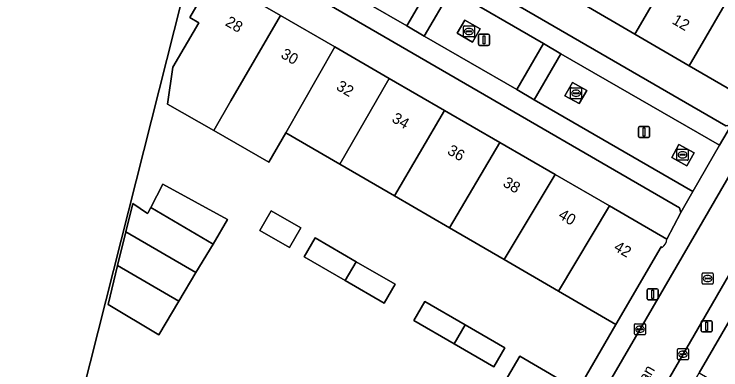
# Model space of a CAD drawing. Extents: x 160023 to 161302, y 384750 to 385707.
# Drawn here: x 160259.3 to 160323.3, y 385038.4 to 385070.6 of the extents above; entities that cross this region are included whole.
import ezdxf

# ---------------------------------------------------------------- set-up
doc = ezdxf.new("R2010")
doc.units = 0
for name, color, linetype in [('IMGEO_Erf', 7, 'Continuous'), ('IMGEO_Grasland_overig', 7, 'Continuous'), ('IMGEO_Groenvoorziening', 7, 'Continuous'), ('IMGEO_Hek', 7, 'Continuous'), ('IMGEO_Kolk', 7, 'Continuous'), ('IMGEO_Lichtmast', 7, 'Continuous'), ('IMGEO_Muur', 7, 'Continuous'), ('IMGEO_Openbare_ruimte_label', 7, 'Continuous'), ('IMGEO_Pand', 7, 'Continuous'), ('IMGEO_Pand_nummerreeks', 7, 'Continuous'), ('IMGEO_Rijbaan_lokaal_open', 7, 'Continuous'), ('IMGEO_Rioolput', 7, 'Continuous'), ('IMGEO_Voetpad_open', 7, 'Continuous')]:
    doc.layers.add(name, color=color, linetype=linetype)

msp = doc.modelspace()

# ---------------------------------------------------------------- linework, layer by layer
at = {"layer": 'IMGEO_Erf'}
for points in [[(160293.095, 385145.525), (160266.916, 385041.926), (160261.202, 385019.264)], [(160278.83, 385086.496), (160323.699, 385060.519), (160324.22, 385060.605), (160325.557, 385062.957), (160320.404, 385065.947), (160315.483, 385068.802), (160310.552, 385071.662)], [(160278.193, 385073.523), (160283.41, 385070.503), (160288.342, 385067.649), (160293.266, 385064.799), (160298.25, 385061.914), (160303.277, 385059.004), (160308.254, 385056.123), (160313.176, 385053.274), (160318.364, 385050.271), (160319.638, 385052.685), (160319.512, 385053.082), (160276.629, 385077.974)], [(160309.764, 385035.682), (160313.763, 385042.544), (160308.557, 385045.567), (160303.656, 385048.412), (160298.712, 385051.282), (160293.738, 385054.17), (160288.784, 385057.046), (160283.9, 385059.882), (160282.379, 385057.222), (160277.378, 385060.082), (160273.2, 385062.472), (160273.687, 385065.811), (160276.023, 385069.833), (160275.211, 385070.305), (160277.161, 385073.661)], [(160303.969, 385037.777), (160305.078, 385039.676), (160308.618, 385037.609)]]:
    msp.add_lwpolyline(points, dxfattribs=at)
for points in [[(160277.317, 385049.825), (160275.767, 385047.232), (160274.218, 385044.64), (160272.405, 385041.605), (160267.824, 385044.342), (160268.686, 385047.875), (160269.434, 385050.937), (160270.054, 385053.478), (160271.401, 385052.58), (160271.415, 385052.602), (160271.684, 385053.12), (160272.786, 385055.244), (160278.636, 385052.033)], [(160281.548, 385051.053), (160282.565, 385052.826), (160285.266, 385051.276), (160284.249, 385049.503)], [(160285.558, 385048.661), (160286.549, 385050.376), (160290.273, 385048.224), (160293.793, 385046.189), (160292.802, 385044.474), (160289.276, 385046.512)], [(160296.467, 385044.618), (160300.131, 385042.501), (160303.711, 385040.431), (160302.72, 385038.716), (160299.116, 385040.799), (160295.476, 385042.903)]]:
    msp.add_lwpolyline(points, close=True, dxfattribs=at)
at = {"layer": 'IMGEO_Grasland_overig'}
msp.add_lwpolyline([(160263.258, 385128.704), (160254.185, 385092.511), (160247.686, 385066.356), (160240.011, 385035.841), (160232.89, 385007.459), (160237.23, 385006.236), (160253.525, 385012.336), (160257.45, 385014.824), (160260.583, 385016.811), (160261.202, 385019.264), (160266.916, 385041.926), (160293.095, 385145.525)], dxfattribs=at)
at = {"layer": 'IMGEO_Groenvoorziening'}
for points in [[(160283.409, 385081.75), (160280.973, 385077.566), (160294.841, 385069.555), (160297.275, 385073.716)], [(160298.861, 385072.807), (160296.418, 385068.634), (160304.793, 385063.794), (160307.217, 385067.951)], [(160299.392, 385068.892), (160300.083, 385070.085), (160301.474, 385069.29), (160300.786, 385068.091)], [(160308.793, 385067.033), (160306.362, 385062.878), (160320.723, 385054.571), (160323.131, 385058.752)], [(160309.152, 385063.222), (160309.83, 385064.427), (160311.131, 385063.723), (160310.452, 385062.522)], [(160318.809, 385057.635), (160319.458, 385058.836), (160320.847, 385058.076), (160320.177, 385056.886)]]:
    msp.add_lwpolyline(points, close=True, dxfattribs=at)
at = {"layer": 'IMGEO_Hek'}
for points in [[(160293.095, 385145.525), (160266.916, 385041.926)], [(160261.202, 385019.264), (160266.916, 385041.926)]]:
    msp.add_lwpolyline(points, dxfattribs=at)
at = {"layer": 'IMGEO_Kolk'}
for p, q in [((160299.964, 385068.628), (160299.964, 385069.48)), ((160300.039, 385069.554), (160300.891, 385069.554)), ((160300.965, 385069.48), (160300.965, 385068.628)), ((160300.223, 385069.048), (160300.223, 385069.06)), ((160300.661, 385069.011), (160300.263, 385069.011)), ((160300.266, 385069.097), (160300.664, 385069.097)), ((160300.475, 385068.774), (160300.45, 385068.774)), ((160300.452, 385069.334), (160300.477, 385069.334)), ((160300.707, 385069.06), (160300.707, 385069.048)), ((160300.891, 385068.554), (160300.039, 385068.554)), ((160309.66, 385063.034), (160309.66, 385063.886)), ((160309.735, 385063.96), (160310.587, 385063.96)), ((160310.148, 385063.74), (160310.173, 385063.74)), ((160310.661, 385063.886), (160310.661, 385063.034)), ((160309.919, 385063.454), (160309.919, 385063.466)), ((160310.357, 385063.417), (160309.959, 385063.417)), ((160309.962, 385063.503), (160310.36, 385063.503)), ((160310.171, 385063.18), (160310.146, 385063.18)), ((160310.403, 385063.466), (160310.403, 385063.454)), ((160310.587, 385062.96), (160309.735, 385062.96)), ((160319.288, 385057.471), (160319.288, 385058.323)), ((160319.363, 385058.397), (160320.215, 385058.397)), ((160319.547, 385057.891), (160319.547, 385057.903)), ((160319.59, 385057.94), (160319.988, 385057.94)), ((160319.776, 385058.177), (160319.801, 385058.177)), ((160320.031, 385057.903), (160320.031, 385057.891)), ((160320.289, 385058.323), (160320.289, 385057.471)), ((160320.215, 385057.397), (160319.363, 385057.397)), ((160319.985, 385057.854), (160319.587, 385057.854)), ((160319.799, 385057.617), (160319.774, 385057.617)), ((160315.44, 385041.684), (160315.44, 385042.536)), ((160315.515, 385042.61), (160316.367, 385042.61)), ((160316.441, 385042.536), (160316.441, 385041.684)), ((160315.699, 385042.104), (160315.699, 385042.116)), ((160316.137, 385042.067), (160315.739, 385042.067)), ((160315.742, 385042.153), (160316.14, 385042.153)), ((160315.928, 385042.39), (160315.953, 385042.39)), ((160316.183, 385042.116), (160316.183, 385042.104)), ((160316.367, 385041.61), (160315.515, 385041.61)), ((160315.951, 385041.83), (160315.926, 385041.83)), ((160319.333, 385039.435), (160319.333, 385040.287)), ((160319.408, 385040.361), (160320.26, 385040.361)), ((160319.821, 385040.141), (160319.846, 385040.141)), ((160320.334, 385040.287), (160320.334, 385039.435)), ((160320.26, 385039.361), (160319.408, 385039.361)), ((160319.592, 385039.855), (160319.592, 385039.867)), ((160320.03, 385039.818), (160319.632, 385039.818)), ((160319.635, 385039.904), (160320.033, 385039.904)), ((160319.844, 385039.581), (160319.819, 385039.581)), ((160320.076, 385039.867), (160320.076, 385039.855))]:
    msp.add_line(p, q, dxfattribs=at)
for points in [[(160299.964, 385068.628), (160299.964, 385069.48)], [(160300.039, 385069.554), (160300.891, 385069.554)], [(160300.965, 385069.48), (160300.965, 385068.628)], [(160300.891, 385068.554), (160300.039, 385068.554)], [(160309.66, 385063.034), (160309.66, 385063.886)], [(160309.735, 385063.96), (160310.587, 385063.96)], [(160310.661, 385063.886), (160310.661, 385063.034)], [(160310.587, 385062.96), (160309.735, 385062.96)], [(160319.288, 385057.471), (160319.288, 385058.323)], [(160319.363, 385058.397), (160320.215, 385058.397)], [(160320.289, 385058.323), (160320.289, 385057.471)], [(160320.215, 385057.397), (160319.363, 385057.397)], [(160315.44, 385041.684), (160315.44, 385042.536)], [(160315.515, 385042.61), (160316.367, 385042.61)], [(160316.441, 385042.536), (160316.441, 385041.684)], [(160316.367, 385041.61), (160315.515, 385041.61)], [(160319.333, 385039.435), (160319.333, 385040.287)], [(160319.408, 385040.361), (160320.26, 385040.361)], [(160320.334, 385040.287), (160320.334, 385039.435)], [(160320.26, 385039.361), (160319.408, 385039.361)]]:
    msp.add_lwpolyline(points, dxfattribs=at)
for centre, radius, start, end in [((160300.041, 385069.478), 0.0765, 91.55205, 178.44795), ((160300.041, 385069.478), 0.0765, 91.55205, 178.44795), ((160300.889, 385069.478), 0.0765, 1.55205, 88.44795), ((160300.889, 385069.478), 0.0765, 1.55205, 88.44795), ((160300.263, 385069.057), 0.0403, 85.87752, 175.75265), ((160300.26, 385069.047), 0.0366, 178.93798, 274.71019), ((160300.664, 385069.054), 0.043, 264.86636, 352.45326), ((160300.668, 385069.059), 0.0386, 1.73085, 96.63898), ((160300.041, 385068.63), 0.0765, 181.55205, 268.44795), ((160300.041, 385068.63), 0.0765, 181.55205, 268.44795), ((160300.889, 385068.63), 0.0765, 271.55205, 358.44795), ((160300.889, 385068.63), 0.0765, 271.55205, 358.44795), ((160309.737, 385063.884), 0.0765, 91.55205, 178.44795), ((160309.737, 385063.884), 0.0765, 91.55205, 178.44795), ((160310.585, 385063.884), 0.0765, 1.55205, 88.44795), ((160310.585, 385063.884), 0.0765, 1.55205, 88.44795), ((160309.737, 385063.036), 0.0765, 181.55205, 268.44795), ((160309.737, 385063.036), 0.0765, 181.55205, 268.44795), ((160309.959, 385063.463), 0.0403, 85.87752, 175.75265), ((160309.956, 385063.453), 0.0366, 178.93798, 274.71019), ((160310.36, 385063.46), 0.043, 264.86636, 352.45326), ((160310.364, 385063.465), 0.0386, 1.73085, 96.63898), ((160310.585, 385063.036), 0.0765, 271.55205, 358.44795), ((160310.585, 385063.036), 0.0765, 271.55205, 358.44795), ((160319.365, 385058.321), 0.0765, 91.55205, 178.44795), ((160319.365, 385058.321), 0.0765, 91.55205, 178.44795), ((160319.587, 385057.9), 0.0403, 85.87752, 175.75265), ((160319.584, 385057.89), 0.0366, 178.93798, 274.71019), ((160319.988, 385057.897), 0.043, 264.86636, 352.45326), ((160319.992, 385057.902), 0.0386, 1.73085, 96.63898), ((160320.213, 385058.321), 0.0765, 1.55205, 88.44795), ((160320.213, 385058.321), 0.0765, 1.55205, 88.44795), ((160319.365, 385057.473), 0.0765, 181.55205, 268.44795), ((160319.365, 385057.473), 0.0765, 181.55205, 268.44795), ((160320.213, 385057.473), 0.0765, 271.55205, 358.44795), ((160320.213, 385057.473), 0.0765, 271.55205, 358.44795), ((160315.517, 385042.534), 0.0765, 91.55205, 178.44795), ((160315.517, 385042.534), 0.0765, 91.55205, 178.44795), ((160316.365, 385042.534), 0.0765, 1.55205, 88.44795), ((160316.365, 385042.534), 0.0765, 1.55205, 88.44795), ((160315.739, 385042.113), 0.0403, 85.87752, 175.75265), ((160315.736, 385042.103), 0.0366, 178.93798, 274.71019), ((160316.14, 385042.11), 0.043, 264.86636, 352.45326), ((160316.144, 385042.115), 0.0386, 1.73085, 96.63898), ((160315.517, 385041.686), 0.0765, 181.55205, 268.44795), ((160315.517, 385041.686), 0.0765, 181.55205, 268.44795), ((160316.365, 385041.686), 0.0765, 271.55205, 358.44795), ((160316.365, 385041.686), 0.0765, 271.55205, 358.44795), ((160319.41, 385040.285), 0.0765, 91.55205, 178.44795), ((160319.41, 385040.285), 0.0765, 91.55205, 178.44795), ((160320.258, 385040.285), 0.0765, 1.55205, 88.44795), ((160320.258, 385040.285), 0.0765, 1.55205, 88.44795), ((160319.41, 385039.437), 0.0765, 181.55205, 268.44795), ((160319.41, 385039.437), 0.0765, 181.55205, 268.44795), ((160319.632, 385039.864), 0.0403, 85.87752, 175.75265), ((160319.629, 385039.854), 0.0366, 178.93798, 274.71019), ((160320.033, 385039.861), 0.043, 264.86636, 352.45326), ((160320.037, 385039.866), 0.0386, 1.73085, 96.63898), ((160320.258, 385039.437), 0.0765, 271.55205, 358.44795), ((160320.258, 385039.437), 0.0765, 271.55205, 358.44795)]:
    msp.add_arc(centre, radius, start, end, dxfattribs=at)
for centre, major_axis, ratio, start_param, end_param in [((160300.451, 385069.054), (-0.387, 0.002), 0.722429, 4.712389, 7.853982), ((160300.476, 385069.054), (-0.39, 0.002), 0.717154, 1.570796, 4.712389), ((160310.147, 385063.46), (-0.387, 0.002), 0.722429, 4.712389, 7.853982), ((160310.172, 385063.46), (-0.39, 0.002), 0.717154, 1.570796, 4.712389), ((160319.775, 385057.897), (-0.387, 0.002), 0.722429, 4.712389, 7.853982), ((160319.8, 385057.897), (-0.39, 0.002), 0.717154, 1.570796, 4.712389), ((160315.927, 385042.11), (-0.387, 0.002), 0.722429, 4.712389, 7.853982), ((160315.952, 385042.11), (-0.39, 0.002), 0.717154, 1.570796, 4.712389), ((160319.82, 385039.861), (-0.387, 0.002), 0.722429, 4.712389, 7.853982), ((160319.845, 385039.861), (-0.39, 0.002), 0.717154, 1.570796, 4.712389)]:
    msp.add_ellipse(centre, major_axis=major_axis, ratio=ratio, start_param=start_param, end_param=end_param, dxfattribs=at)
at = {"layer": 'IMGEO_Lichtmast'}
for p, q in [((160301.423, 385068.793), (160302.213, 385068.793)), ((160302.213, 385068.793), (160301.423, 385068.793)), ((160301.323, 385067.893), (160301.323, 385068.693)), ((160301.323, 385068.693), (160301.323, 385067.893)), ((160302.313, 385068.693), (160302.313, 385067.893)), ((160302.313, 385067.893), (160302.313, 385068.693)), ((160302.213, 385067.793), (160301.423, 385067.793)), ((160301.423, 385067.793), (160302.213, 385067.793)), ((160315.911, 385060.446), (160316.701, 385060.446)), ((160316.701, 385060.446), (160315.911, 385060.446)), ((160315.811, 385059.546), (160315.811, 385060.346)), ((160315.811, 385060.346), (160315.811, 385059.546)), ((160316.801, 385060.346), (160316.801, 385059.546)), ((160316.801, 385059.546), (160316.801, 385060.346)), ((160316.701, 385059.446), (160315.911, 385059.446)), ((160315.911, 385059.446), (160316.701, 385059.446)), ((160316.685, 385045.767), (160317.475, 385045.767)), ((160317.475, 385045.767), (160316.685, 385045.767)), ((160316.585, 385044.867), (160316.585, 385045.667)), ((160316.585, 385045.667), (160316.585, 385044.867)), ((160317.575, 385045.667), (160317.575, 385044.867)), ((160317.575, 385044.867), (160317.575, 385045.667)), ((160317.475, 385044.767), (160316.685, 385044.767)), ((160316.685, 385044.767), (160317.475, 385044.767)), ((160321.481, 385041.977), (160321.481, 385042.777)), ((160321.481, 385042.777), (160321.481, 385041.977)), ((160321.581, 385042.877), (160322.371, 385042.877)), ((160322.371, 385042.877), (160321.581, 385042.877)), ((160322.471, 385042.777), (160322.471, 385041.977)), ((160322.471, 385041.977), (160322.471, 385042.777)), ((160322.371, 385041.877), (160321.581, 385041.877)), ((160321.581, 385041.877), (160322.371, 385041.877))]:
    msp.add_line(p, q, dxfattribs=at)
for points in [[(160301.743, 385068.668), (160301.893, 385068.668), (160301.893, 385067.918), (160301.743, 385067.918), (160301.743, 385068.668)], [(160316.231, 385060.321), (160316.381, 385060.321), (160316.381, 385059.571), (160316.231, 385059.571), (160316.231, 385060.321)], [(160317.005, 385045.642), (160317.155, 385045.642), (160317.155, 385044.892), (160317.005, 385044.892), (160317.005, 385045.642)], [(160321.901, 385042.752), (160322.051, 385042.752), (160322.051, 385042.002), (160321.901, 385042.002), (160321.901, 385042.752)]]:
    msp.add_lwpolyline(points, dxfattribs=at)
for centre, start, end in [((160301.423, 385068.693), 90, 180), ((160301.423, 385068.693), 90, 180), ((160302.213, 385068.693), 0, 90), ((160302.213, 385068.693), 360, 90), ((160301.423, 385067.893), 180, 270), ((160301.423, 385067.893), 180, 270), ((160302.213, 385067.893), 270, 0), ((160302.213, 385067.893), 270, 0), ((160315.911, 385060.346), 90, 180), ((160315.911, 385060.346), 90, 180), ((160316.701, 385060.346), 0, 90), ((160316.701, 385060.346), 360, 90), ((160315.911, 385059.546), 180, 270), ((160315.911, 385059.546), 180, 270), ((160316.701, 385059.546), 270, 0), ((160316.701, 385059.546), 270, 0), ((160316.685, 385045.667), 90, 180), ((160316.685, 385045.667), 90, 180), ((160317.475, 385045.667), 0, 90), ((160317.475, 385045.667), 360, 90), ((160316.685, 385044.867), 180, 270), ((160316.685, 385044.867), 180, 270), ((160317.475, 385044.867), 270, 0), ((160317.475, 385044.867), 270, 0), ((160321.581, 385042.777), 90, 180), ((160321.581, 385042.777), 90, 180), ((160322.371, 385042.777), 0, 90), ((160322.371, 385042.777), 360, 90), ((160321.581, 385041.977), 180, 270), ((160321.581, 385041.977), 180, 270), ((160322.371, 385041.977), 270, 0), ((160322.371, 385041.977), 270, 0)]:
    msp.add_arc(centre, 0.1, start, end, dxfattribs=at)
at = {"layer": 'IMGEO_Muur'}
msp.add_lwpolyline([(160313.763, 385042.544), (160309.764, 385035.682), (160308.061, 385036.655)], dxfattribs=at)
at = {"layer": 'IMGEO_Pand'}
for points in [[(160310.552, 385071.662), (160315.483, 385068.802), (160319.989, 385076.601), (160315.063, 385079.461)], [(160324.913, 385073.741), (160319.989, 385076.601), (160315.483, 385068.802), (160320.404, 385065.947)], [(160283.41, 385070.503), (160278.193, 385073.523), (160277.974, 385073.189), (160277.161, 385073.661), (160275.211, 385070.305), (160276.023, 385069.833), (160273.687, 385065.811), (160273.2, 385062.472), (160277.378, 385060.082), (160278.931, 385062.766)], [(160288.342, 385067.649), (160283.41, 385070.503), (160278.931, 385062.766), (160277.378, 385060.082), (160282.379, 385057.222), (160283.9, 385059.882)], [(160283.9, 385059.882), (160288.784, 385057.046), (160293.266, 385064.799), (160288.342, 385067.649)], [(160288.784, 385057.046), (160293.738, 385054.17), (160298.25, 385061.914), (160293.266, 385064.799)], [(160293.738, 385054.17), (160298.712, 385051.282), (160303.277, 385059.004), (160298.25, 385061.914)], [(160308.254, 385056.123), (160303.277, 385059.004), (160298.712, 385051.282), (160303.656, 385048.412)], [(160313.176, 385053.274), (160308.254, 385056.123), (160303.656, 385048.412), (160308.557, 385045.567)], [(160277.317, 385049.825), (160278.636, 385052.033), (160272.786, 385055.244), (160271.684, 385053.12)], [(160275.767, 385047.232), (160277.317, 385049.825), (160271.684, 385053.12), (160271.415, 385052.602), (160271.401, 385052.58), (160270.054, 385053.478), (160269.434, 385050.937)], [(160281.548, 385051.053), (160284.249, 385049.503), (160285.266, 385051.276), (160282.565, 385052.826)], [(160274.218, 385044.64), (160275.767, 385047.232), (160269.434, 385050.937), (160268.686, 385047.875)], [(160286.549, 385050.376), (160285.558, 385048.661), (160289.276, 385046.512), (160290.273, 385048.224)], [(160268.686, 385047.875), (160267.824, 385044.342), (160272.405, 385041.605), (160274.218, 385044.64)], [(160292.802, 385044.474), (160293.793, 385046.189), (160290.273, 385048.224), (160289.276, 385046.512)], [(160296.467, 385044.618), (160295.476, 385042.903), (160299.116, 385040.799), (160300.131, 385042.501)], [(160302.72, 385038.716), (160303.711, 385040.431), (160300.131, 385042.501), (160299.116, 385040.799)], [(160308.061, 385036.655), (160308.618, 385037.609), (160305.078, 385039.676), (160303.969, 385037.777), (160307.513, 385035.716)]]:
    msp.add_lwpolyline(points, close=True, dxfattribs=at)
for points in [[(160326.107, 385063.646), (160326.01, 385063.697), (160330.09, 385070.735), (160324.913, 385073.741), (160320.404, 385065.947), (160325.557, 385062.957), (160325.666, 385062.894)], [(160318.364, 385050.271), (160313.176, 385053.274), (160308.557, 385045.567), (160313.763, 385042.544), (160317.844, 385049.573), (160317.939, 385049.512)], [(160325.286, 385045.271), (160325.384, 385045.224), (160321.307, 385038.162), (160326.462, 385035.188), (160330.97, 385042.98), (160325.824, 385045.965), (160325.713, 385046.029)]]:
    msp.add_lwpolyline(points, dxfattribs=at)
msp.add_arc((160317.382, 385050.322), 0.983, 304.5065, 357.00044, dxfattribs=at)
at = {"layer": 'IMGEO_Rijbaan_lokaal_open'}
for points in [[(160352.099, 385104.5), (160351.183, 385102.92), (160342.043, 385087.129), (160339.387, 385082.576), (160338.894, 385081.699), (160336.41, 385077.395), (160333.739, 385072.8), (160315.942, 385042.109), (160311.381, 385034.254), (160308.757, 385029.746), (160308.283, 385028.896), (160306.745, 385026.259), (160297.459, 385010.254), (160295.452, 385006.786), (160294.418, 385005.017)], [(160298.133, 385002.441), (160299.328, 385004.495), (160301.364, 385007.975), (160310.622, 385023.967), (160312.148, 385026.623), (160312.692, 385027.574), (160315.342, 385032.116), (160319.833, 385039.862), (160338.122, 385071.424)]]:
    msp.add_lwpolyline(points, dxfattribs=at)
at = {"layer": 'IMGEO_Rioolput'}
for p, q in [((160321.565, 385046.278), (160321.565, 385047.13)), ((160321.64, 385047.204), (160322.492, 385047.204)), ((160322.566, 385047.13), (160322.566, 385046.278)), ((160321.824, 385046.698), (160321.824, 385046.71)), ((160322.262, 385046.661), (160321.864, 385046.661)), ((160321.867, 385046.747), (160322.265, 385046.747)), ((160322.076, 385046.424), (160322.051, 385046.424)), ((160322.053, 385046.984), (160322.078, 385046.984)), ((160322.308, 385046.71), (160322.308, 385046.698)), ((160322.492, 385046.204), (160321.64, 385046.204))]:
    msp.add_line(p, q, dxfattribs=at)
for points in [[(160321.565, 385046.278), (160321.565, 385047.13)], [(160321.64, 385047.204), (160322.492, 385047.204)], [(160322.566, 385047.13), (160322.566, 385046.278)], [(160322.492, 385046.204), (160321.64, 385046.204)]]:
    msp.add_lwpolyline(points, dxfattribs=at)
for centre, radius, start, end in [((160321.642, 385047.128), 0.0765, 91.55205, 178.44795), ((160321.642, 385047.128), 0.0765, 91.55205, 178.44795), ((160322.49, 385047.128), 0.0765, 1.55205, 88.44795), ((160322.49, 385047.128), 0.0765, 1.55205, 88.44795), ((160321.864, 385046.707), 0.0403, 85.87752, 175.75265), ((160321.861, 385046.697), 0.0366, 178.93798, 274.71019), ((160322.265, 385046.704), 0.043, 264.86636, 352.45326), ((160322.269, 385046.709), 0.0386, 1.73085, 96.63898), ((160321.642, 385046.28), 0.0765, 181.55205, 268.44795), ((160321.642, 385046.28), 0.0765, 181.55205, 268.44795), ((160322.49, 385046.28), 0.0765, 271.55205, 358.44795), ((160322.49, 385046.28), 0.0765, 271.55205, 358.44795)]:
    msp.add_arc(centre, radius, start, end, dxfattribs=at)
for centre, major_axis, ratio, start_param, end_param in [((160322.052, 385046.704), (-0.387, 0.002), 0.722429, 4.712389, 7.853982), ((160322.077, 385046.704), (-0.39, 0.002), 0.717154, 1.570796, 4.712389)]:
    msp.add_ellipse(centre, major_axis=major_axis, ratio=ratio, start_param=start_param, end_param=end_param, dxfattribs=at)
at = {"layer": 'IMGEO_Voetpad_open'}
for points in [[(160283.409, 385081.75), (160297.275, 385073.716), (160298.861, 385072.807), (160307.217, 385067.951), (160308.793, 385067.033), (160323.131, 385058.752), (160324.22, 385060.605), (160323.699, 385060.519), (160278.83, 385086.496), (160276.629, 385077.974), (160319.512, 385053.082), (160319.638, 385052.685), (160320.723, 385054.571), (160306.362, 385062.878), (160304.793, 385063.794), (160296.418, 385068.634), (160294.841, 385069.555), (160280.973, 385077.566)], [(160298.861, 385072.807), (160297.275, 385073.716), (160294.841, 385069.555), (160296.418, 385068.634)], [(160300.786, 385068.091), (160301.474, 385069.29), (160300.083, 385070.085), (160299.392, 385068.892)], [(160308.793, 385067.033), (160307.217, 385067.951), (160304.793, 385063.794), (160306.362, 385062.878)], [(160310.452, 385062.522), (160311.131, 385063.723), (160309.83, 385064.427), (160309.152, 385063.222)], [(160320.177, 385056.886), (160320.847, 385058.076), (160319.458, 385058.836), (160318.809, 385057.635)]]:
    msp.add_lwpolyline(points, close=True, dxfattribs=at)
for points in [[(160343.285, 385080.295), (160342.782, 385079.444), (160340.106, 385074.885), (160338.122, 385071.424), (160319.833, 385039.862), (160315.342, 385032.116), (160312.692, 385027.574), (160312.148, 385026.623)], [(160308.283, 385028.896), (160308.757, 385029.746), (160311.381, 385034.254), (160315.942, 385042.109), (160333.739, 385072.8)], [(160325.666, 385062.894), (160325.557, 385062.957), (160324.22, 385060.605), (160323.131, 385058.752), (160320.723, 385054.571), (160319.638, 385052.685), (160318.364, 385050.271)], [(160317.939, 385049.512), (160317.844, 385049.573), (160313.763, 385042.544), (160309.764, 385035.682), (160308.061, 385036.655), (160307.513, 385035.716), (160305.276, 385031.847), (160301.832, 385025.909), (160298.513, 385020.188), (160295.214, 385014.5), (160291.605, 385008.277), (160290.982, 385007.784), (160288.671, 385003.86)], [(160300.306, 384997.12), (160301.947, 385000), (160302.566, 385001.087), (160302.587, 385001.917), (160306.193, 385008.153), (160309.494, 385013.861), (160312.785, 385019.552), (160316.226, 385025.503), (160318.446, 385029.357), (160319.024, 385030.345), (160317.354, 385031.285), (160321.307, 385038.162), (160325.384, 385045.224), (160325.286, 385045.271)]]:
    msp.add_lwpolyline(points, dxfattribs=at)
msp.add_arc((160317.382, 385050.322), 0.983, 304.5065, 357.00044, dxfattribs=at)

# ---------------------------------------------------------------- texts
at = {"layer": 'IMGEO_Openbare_ruimte_label'}
msp.add_text('Jan Duikerlaan', height=1, rotation=59.66519, dxfattribs=at).set_placement((160312.825, 385030.79))
at = {"layer": 'IMGEO_Pand_nummerreeks'}
for s, rotation, p in [('28', 329.9369, (160278.348, 385069.644)), ('12', 329.87936, (160318.767, 385069.81)), ('30', 329.9369, (160283.369, 385066.737)), ('32', 329.93665, (160288.386, 385063.833)), ('34', 329.93665, (160293.41, 385060.925)), ('36', 329.93665, (160298.431, 385058.019)), ('38', 329.93665, (160303.455, 385055.11)), ('40', 329.93665, (160308.476, 385052.204)), ('42', 329.93665, (160313.493, 385049.3))]:
    msp.add_text(s, height=1, rotation=rotation, dxfattribs=at).set_placement(p)

doc.saveas('drawing.dxf')
